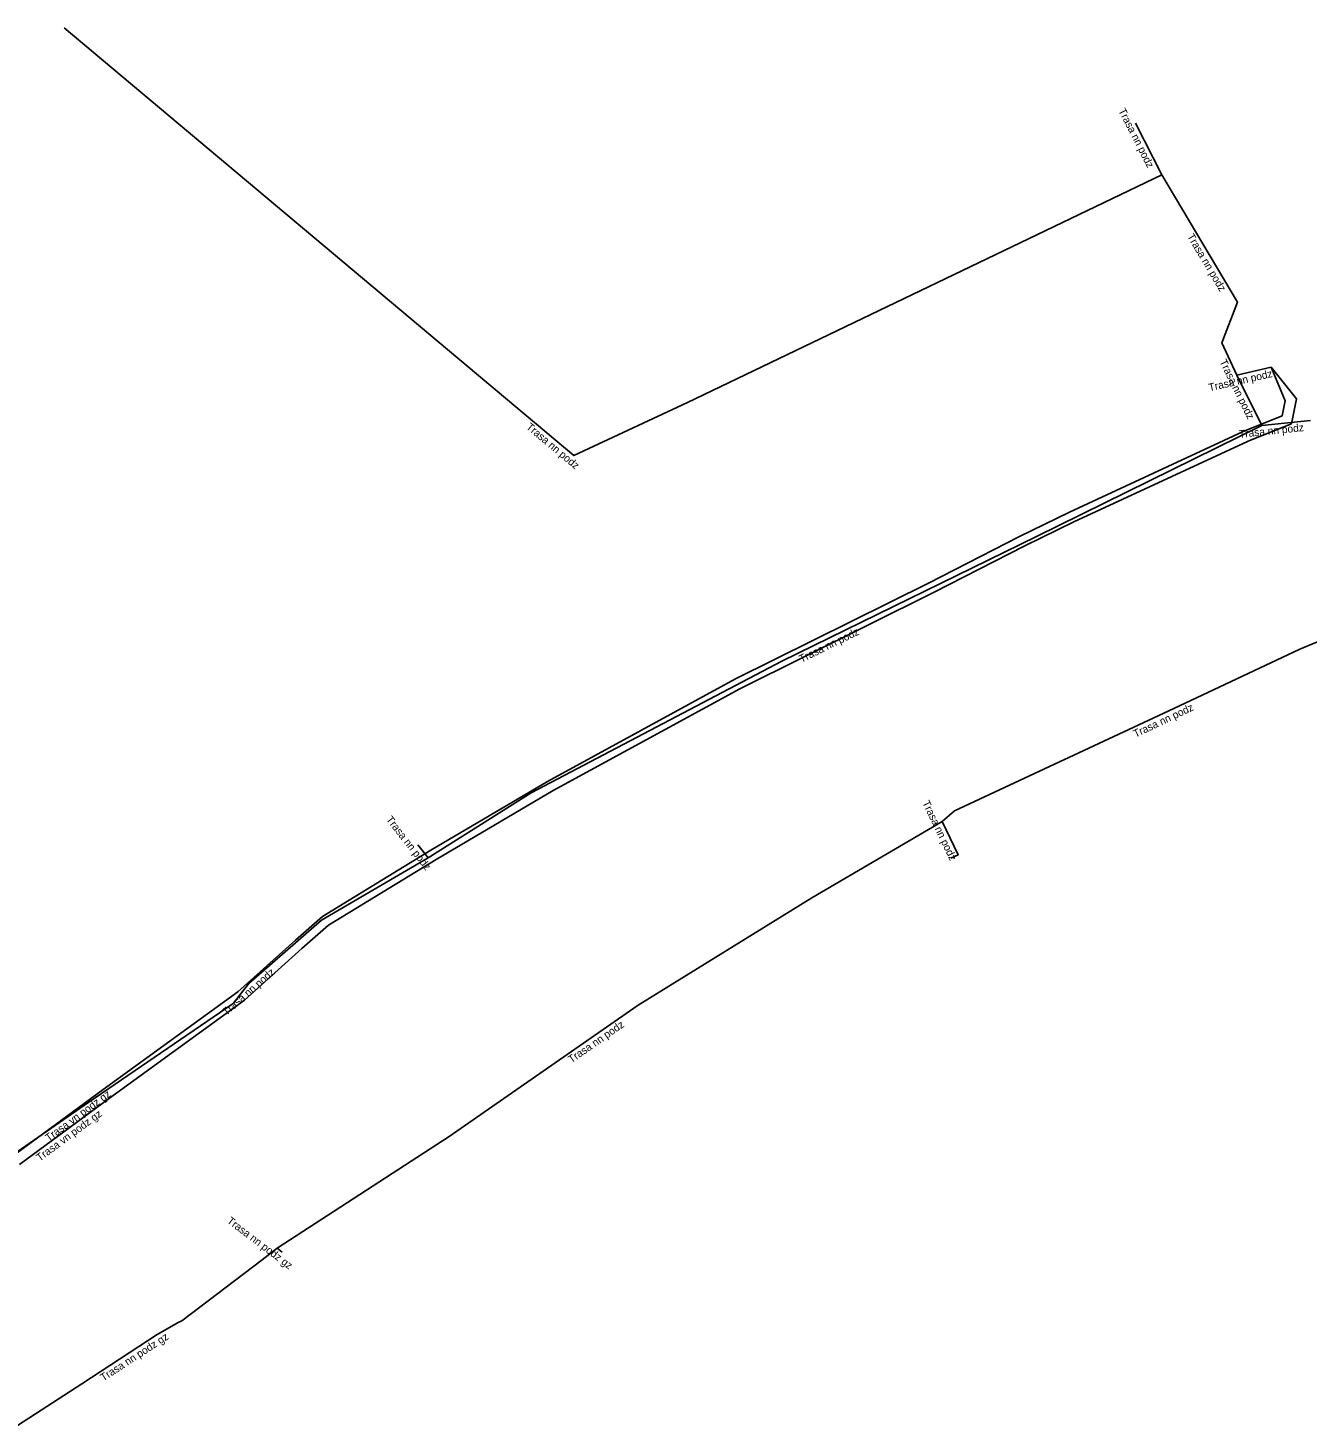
# Model space of a CAD drawing. Extents: x -711262 to -710488, y -1025222 to -1024810.
# Drawn here: x -710915.5 to -710831.5, y -1025018.1 to -1024926.3 of the extents above; entities that cross this region are included whole.
import ezdxf

# ---------------------------------------------------------------- set-up
doc = ezdxf.new("R2010")
doc.units = 0
for name, color, linetype in [('Popiskový text - Ostatní atributy Trasy', 7, 'Continuous'), ('Spojnice NN', 7, 'Continuous'), ('Spojnice VN', 7, 'Continuous')]:
    doc.layers.add(name, color=color, linetype=linetype)

msp = doc.modelspace()

# ---------------------------------------------------------------- linework, layer by layer
at = {"layer": 'Spojnice NN'}
for points in [[(-710841.07, -1024935.94), (-710872.19, -1024950.88), (-710879.64, -1024954.36), (-710913.07, -1024926.309)], [(-710841.07, -1024935.94), (-710842.79, -1024932.55)], [(-710841.07, -1024935.94), (-710836.11, -1024944.3), (-710837.14, -1024946.97), (-710836.15, -1024949.07)], [(-710836.15, -1024949.07), (-710833.89, -1024948.554)], [(-710836.15, -1024949.07), (-710834.52, -1024952.39)], [(-710889.2, -1024980.75), (-710882.45, -1024976.47), (-710865.99, -1024967.85), (-710849.3, -1024959.67), (-710834.52, -1024952.39)], [(-710834.52, -1024952.39), (-710831.33, -1024952.05)], [(-710824.71, -1024964.02), (-710832.03, -1024967.05), (-710840.28, -1024970.95), (-710854.68, -1024977.66), (-710855.49, -1024978.35)], [(-710855.49, -1024978.35), (-710864.04, -1024983.37), (-710875.43, -1024990.4), (-710887.83, -1024999.01), (-710899.11, -1025006.35)], [(-710855.49, -1024978.35), (-710854.44, -1024980.55), (-710854.91, -1024980.76)], [(-710889.2, -1024980.75), (-710889.88, -1024979.88)], [(-710911.47, -1024996.77), (-710902, -1024990.3), (-710900.97, -1024988.98), (-710896.2, -1024984.83), (-710889.2, -1024980.75)], [(-710924.808, -1025005.986), (-710911.47, -1024996.77)], [(-710899.11, -1025006.35), (-710900.09, -1025007.1), (-710905.35, -1025011.12), (-710905.55, -1025011.2), (-710906.97, -1025012.01), (-710911.93, -1025015.25), (-710916.14, -1025017.98), (-710916.36, -1025018.14)], [(-710898.78, -1025006.6), (-710899.11, -1025006.35)]]:
    msp.add_lwpolyline(points, dxfattribs=at)
at = {"layer": 'Spojnice VN'}
for points in [[(-710916.408, -1025000.272), (-710910.523, -1024995.938), (-710901.678, -1024989.525), (-710897.91, -1024986.139), (-710896.141, -1024984.591), (-710889.026, -1024980.245), (-710881.38, -1024975.739), (-710869.031, -1024968.992), (-710856.381, -1024962.723), (-710850.404, -1024959.671), (-710847.124, -1024958.063), (-710835.773, -1024952.804), (-710835.522, -1024952.689), (-710833.182, -1024951.759), (-710832.978, -1024950.765), (-710833.89, -1024948.554)], [(-710916.017, -1025000.85), (-710910.103, -1024996.497), (-710901.241, -1024990.075), (-710897.483, -1024986.696), (-710895.734, -1024985.166), (-710888.681, -1024980.857), (-710881.006, -1024976.334), (-710868.766, -1024969.646), (-710856.042, -1024963.338), (-710850.053, -1024960.277), (-710846.838, -1024958.698), (-710835.462, -1024953.434), (-710835.257, -1024953.339), (-710832.567, -1024952.265), (-710832.24, -1024950.636), (-710833.89, -1024948.554)]]:
    msp.add_lwpolyline(points, dxfattribs=at)

# ---------------------------------------------------------------- texts
at = {"layer": 'Popiskový text - Ostatní atributy Trasy'}
for s, rotation, p in [('Trasa nn podz', 296.90208, (-710843.934, -1024931.732)), ('Trasa nn podz', 300.68072, (-710839.433, -1024939.974)), ('Trasa nn podz', 296.14937, (-710837.306, -1024948.191)), ('Trasa nn podz', 12.85056, (-710837.944, -1024950.146)), ('Trasa nn podz', 319.99989, (-710882.812, -1024952.546)), ('Trasa nn podz', 6.08379, (-710835.986, -1024953.2)), ('Trasa nn podz', 26.11011, (-710864.718, -1024967.951)), ('Trasa nn podz', 25.30138, (-710842.804, -1024972.862)), ('Trasa nn podz', 295.51387, (-710856.796, -1024977.122)), ('Trasa nn podz', 308.01151, (-710891.99, -1024978.235)), ('Trasa nn podz', 41.02395, (-710902.435, -1024991.116)), ('Trasa nn podz', 34.77437, (-710879.803, -1024994.228)), ('Trasa vn podz gz', 36.36974, (-710914.093, -1024999.374)), ('Trasa vn podz gz', 36.35493, (-710914.681, -1025000.673)), ('Trasa nn podz gz', 322.85331, (-710902.442, -1025004.642)), ('Trasa nn podz gz', 33.15361, (-710910.506, -1025015.097))]:
    msp.add_text(s, height=0.5, rotation=rotation, dxfattribs=at).set_placement(p)

doc.saveas('drawing.dxf')
